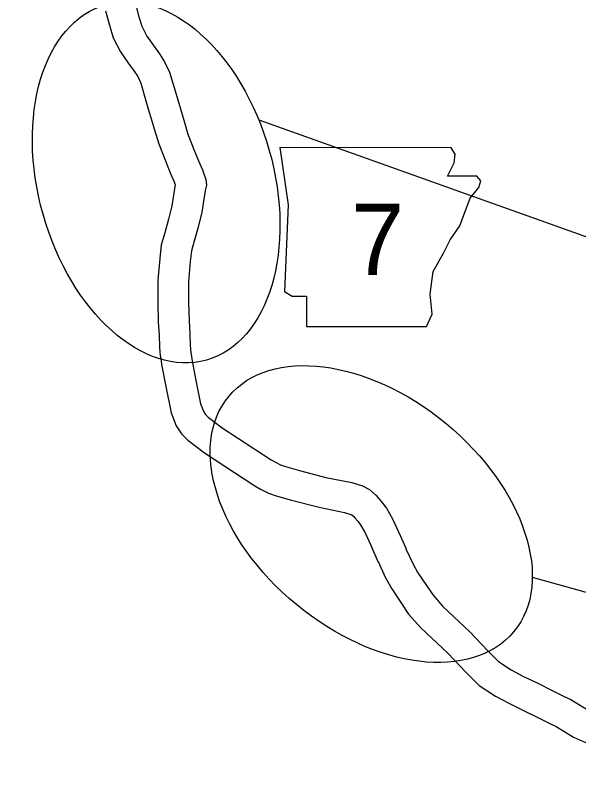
# Model space of a CAD drawing. Extents: x 1373862 to 1377080, y 1164775 to 1170415.
# Drawn here: x 1374149.1 to 1374204.1, y 1170101.4 to 1170176 of the extents above; entities that cross this region are included whole.
import ezdxf

# ---------------------------------------------------------------- set-up
doc = ezdxf.new("R2010")
doc.units = 0
for name, color, linetype in [('1', 7, 'Continuous'), ('Default', 7, 'Continuous'), ('R_Draft', 7, 'Continuous')]:
    doc.layers.add(name, color=color, linetype=linetype)

msp = doc.modelspace()

# ---------------------------------------------------------------- linework, layer by layer
at = {"layer": '1'}
for p in [(1374172.843, 1170165.768), (1374199.554, 1170121.066)]:
    msp.add_line(p, (1374640.758, 1169998.763), dxfattribs=at)
at = {"layer": 'Default'}
for points in [[(1374160.774, 1170177.243), (1374161.143, 1170175.854), (1374161.427, 1170174.916), (1374161.908, 1170173.963), (1374162.553, 1170173.042), (1374163.156, 1170172.222), (1374163.649, 1170171.454), (1374164.126, 1170170.443), (1374164.765, 1170168.267), (1374165.514, 1170165.736), (1374165.917, 1170164.387), (1374166.502, 1170162.872), (1374166.96, 1170161.761), (1374167.334, 1170160.892), (1374167.458, 1170160.6), (1374167.687, 1170159.929), (1374167.736, 1170159.4), (1374167.619, 1170158.869), (1374167.294, 1170156.747), (1374166.915, 1170155.279), (1374166.54, 1170153.907), (1374166.256, 1170152.963), (1374166.151, 1170151.933), (1374165.976, 1170149.975), (1374165.975, 1170147.923), (1374166.029, 1170146.125), (1374166.1, 1170144.862), (1374166.129, 1170143.758), (1374166.166, 1170143.353), (1374166.213, 1170142.983), (1374166.262, 1170142.677), (1374166.311, 1170142.367), (1374166.703, 1170140.28), (1374167.163, 1170137.999), (1374167.312, 1170137.631), (1374167.463, 1170137.225), (1374167.63, 1170136.974), (1374167.886, 1170136.716), (1374169.265, 1170135.665), (1374174.042, 1170132.552), (1374174.467, 1170132.296), (1374174.955, 1170132.045), (1374175.441, 1170131.88), (1374176.817, 1170131.498), (1374179.405, 1170130.825), (1374181.946, 1170130.311), (1374182.957, 1170129.999), (1374183.645, 1170129.653), (1374184.278, 1170129.075), (1374184.494, 1170128.822), (1374184.828, 1170128.439), (1374185.326, 1170127.803), (1374185.909, 1170126.773), (1374186.489, 1170125.498), (1374187.226, 1170123.825)], [(1374157.884, 1170176.44), (1374158.257, 1170175.035), (1374158.631, 1170173.797), (1374159.327, 1170172.419), (1374160.116, 1170171.292), (1374160.683, 1170170.522), (1374161.019, 1170169.997), (1374161.314, 1170169.373), (1374161.887, 1170167.419), (1374162.638, 1170164.88), (1374163.077, 1170163.415), (1374163.716, 1170161.759), (1374164.195, 1170160.597), (1374164.575, 1170159.712), (1374164.655, 1170159.526), (1374164.676, 1170159.464), (1374164.351, 1170157.351), (1374164.016, 1170156.05), (1374163.656, 1170154.735), (1374163.3, 1170153.551), (1374163.165, 1170152.218), (1374162.976, 1170150.11), (1374162.974, 1170147.879), (1374163.031, 1170145.996), (1374163.102, 1170144.739), (1374163.132, 1170143.582), (1374163.183, 1170143.027), (1374163.243, 1170142.557), (1374163.299, 1170142.204), (1374163.355, 1170141.854), (1374163.758, 1170139.707), (1374164.277, 1170137.133), (1374164.515, 1170136.544), (1374164.773, 1170135.853), (1374165.293, 1170135.07), (1374165.902, 1170134.455), (1374167.535, 1170133.212), (1374172.449, 1170130.01), (1374173.006, 1170129.674), (1374173.78, 1170129.276), (1374174.555, 1170129.012), (1374176.038, 1170128.6), (1374178.729, 1170127.901), (1374181.205, 1170127.4), (1374181.833, 1170127.206), (1374181.927, 1170127.159), (1374182.118, 1170126.984), (1374182.224, 1170126.86), (1374182.515, 1170126.528), (1374182.825, 1170126.131), (1374183.234, 1170125.409), (1374183.751, 1170124.272), (1374184.48, 1170122.617)], [(1374187.216, 1170123.846), (1374187.871, 1170122.418), (1374188.389, 1170121.499), (1374189.217, 1170120.271), (1374189.857, 1170119.303), (1374190.833, 1170118.218), (1374193.451, 1170115.716), (1374195.213, 1170113.87), (1374196.256, 1170112.833), (1374197.504, 1170112.02), (1374198.623, 1170111.407), (1374200.016, 1170110.733), (1374201.558, 1170109.972), (1374202.594, 1170109.454), (1374203.322, 1170109.103), (1374204.17, 1170108.585), (1374204.993, 1170108.095), (1374205.662, 1170107.78), (1374205.819, 1170107.715), (1374206.154, 1170107.604), (1374206.596, 1170107.477)], [(1374184.489, 1170122.595), (1374185.196, 1170121.054), (1374185.834, 1170119.922), (1374186.723, 1170118.605), (1374187.477, 1170117.464), (1374188.677, 1170116.128), (1374191.329, 1170113.594), (1374193.07, 1170111.77), (1374194.36, 1170110.487), (1374195.962, 1170109.444), (1374197.248, 1170108.739), (1374198.699, 1170108.038), (1374200.223, 1170107.286), (1374201.271, 1170106.762), (1374201.885, 1170106.465), (1374202.621, 1170106.016), (1374203.583, 1170105.443), (1374204.456, 1170105.031), (1374204.779, 1170104.9), (1374205.265, 1170104.739), (1374205.763, 1170104.594)]]:
    msp.add_lwpolyline(points, dxfattribs=at)
msp.add_lwpolyline([(1374174.885, 1170163.056), (1374175.722, 1170157.473), (1374175.35, 1170149.006), (1374176.095, 1170148.54), (1374177.49, 1170148.54), (1374177.49, 1170145.563), (1374189.214, 1170145.563), (1374189.773, 1170146.772), (1374189.587, 1170148.726), (1374189.866, 1170150.96), (1374190.889, 1170152.728), (1374191.541, 1170154.03), (1374192.471, 1170155.426), (1374193.029, 1170156.915), (1374193.495, 1170158.124), (1374194.332, 1170159.148), (1374194.518, 1170159.799), (1374194.146, 1170160.264), (1374191.262, 1170160.264), (1374191.913, 1170161.567), (1374192.006, 1170162.405), (1374191.62, 1170163.048)], close=True, dxfattribs=at)
at = {"layer": 'R_Draft'}
for centre, major_axis in [((1374162.821, 1170159.661), (4.91, -17.376)), ((1374183.827, 1170127.238), (-13.926, 11.493))]:
    msp.add_ellipse(centre, major_axis=major_axis, ratio=0.635834, dxfattribs=at)

# ---------------------------------------------------------------- texts
at = {"layer": 'Default'}
msp.add_text('7', height=6.97, dxfattribs=at).set_placement((1374181.863, 1170150.599))

doc.saveas('drawing.dxf')
